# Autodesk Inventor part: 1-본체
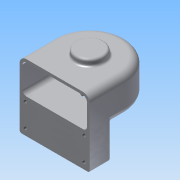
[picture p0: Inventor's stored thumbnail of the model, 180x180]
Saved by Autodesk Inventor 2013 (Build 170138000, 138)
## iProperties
Created: 2015-02
Part Number: 1-본체
Material: 알루미늄 6061
Document SubType Name: Modeling
Designer: Administrator
Density: 2.71 g/cm^3
Mass: 565.472 g
Surface Area: 719.016 cm^2
Volume: 208.661 cm^3
Author: Administrator
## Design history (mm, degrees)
sketch "스케치1"
  geometry: L1 (-50, 0)-(-50, -50); L2 (50, -50)-(50, 0); L3 (-50, -50)-(50, -50); L4 (-34.641, -20)-(-50, -20); L5 (34.641, -20)-(50, -20); L6 (-34.641, -20)-(-34.641, -50); L7 (34.641, -20)-(34.641, -50); A1 r 50 centre (0, 0) between (-50, 0) and (50, 0); A2 r 40 centre (0, 0) between (-34.641, -20) and (34.641, -20); 1 further point
  constraints: 14 end point, 5 perpendicular, 4 point on circle, 4 point on line, 3 tangent, 2 centre point, 2 coincident, 1 collinear, 1 parallel, 1 vertical
  dimensions: "d0" = 50 radius of A1; "d3" = 40 radius of A2; "d4" = 30 distance between parallel lines of L3 L4
extrude "돌출1" new body sketch "스케치1" distance "d5" = 50; taper "d6" = 0 deg
feature "쉘1" dims "d9" = 4
extrude "돌출2" join sketch "스케치1" distance "d7" = 45; taper "d8" = 0 deg
sketch "스케치2"
  geometry: C1 r 25 at (0, 0); A1 r 50 centre (0, 0) between (50, 0) and (-50, 0) reference; A2 r 40 centre (0, 0) between (-34.641, -20) and (34.641, -20) reference
  constraints: 2 coincident, 1 centre point
  dimensions: "d10" = 50 diameter of C1
extrude "돌출3" join sketch "스케치2" distance "d12" = 10; taper "d13" = -20 deg
sketch "스케치3"
  geometry: C1 r 20 at (0, 0); A1 r 50 centre (0, 0) between (50, 0) and (-50, 0) reference
  constraints: 1 centre point, 1 coincident
  dimensions: "d14" = 40 diameter of C1
extrude "돌출4" join sketch "스케치3" distance "d16" = 9; taper "d17" = 0 deg
hole "구멍1" diameter "d20" = 20; stored, may be unused: countersink angle "d24" = 90 deg, drill point angle "d26" = 0 deg; dims "d18" = 10, "d19" = 10, "d21" = 6, "d22" = 28, "d23" = 10, "d25" = 14
hole "구멍2" diameter "d29" = 20; stored, may be unused: countersink angle "d33" = 90 deg, drill point angle "d35" = 0 deg; dims "d27" = 10, "d28" = 10, "d30" = 6, "d31" = 28, "d32" = 8, "d34" = 10
sketch "스케치4"
  geometry: C1 r 14 at (0, 0) reference; C2 r 21.36 at (0, 0) reference; A1 r 18 centre (0, 0) between (0, 18) and (18, 0); 2 further points
  constraints: 4 point on circle, 2 horizontal alignment, 2 vertical alignment, 1 centre point, 1 coincident
  dimensions: "d36" = 36 diameter of A1
hole "구멍3" sketch "스케치4" at (0, 18), (18, 0), (0, -18), (-18, 0) diameter "d38" = 2.459; stored, may be unused: countersink angle "d42" = 90 deg, drill point angle "d44" = 118 deg; dims "d39" = 6, "d40" = 28, "d41" = 8, "d43" = 9
fillet "모깎기2" dims "d46" = 10
fillet "모깎기3" dims "d47" = 3
fillet "모깎기4" dims "d48" = 3
fillet "모깎기5" dims "d49" = 3
chamfer "모따기1" distance "d50" = 1; stored, may be unused: second distance "d51" = 2, angle "d52" = 45 deg
fillet "모깎기6" dims "d53" = 0.3
sketch "스케치5"
  geometry: L1 (87, -95)-(-7, -95) reference; 6 further points
  constraints: 2 horizontal alignment, 2 vertical alignment, 1 midpoint
  dimensions: "d54" = 9 distance from line of L1 point (-1.75, -86); "d55" = 33 distance of point (-1.75, -86) point (-1.75, -53); "d56" = 83.5 distance of point (81.75, -86) point (-1.75, -86); "d57" = 41.75 horizontal distance of point (-1.75, -86) point (40, -95)
hole "구멍4" sketch "스케치5" at (-1.75, -53), (-1.75, -86), (81.75, -53), (81.75, -86) diameter "d58" = 5.134; stored, may be unused: countersink angle "d62" = 90 deg, drill point angle "d64" = 118 deg; dims "d59" = 10, "d60" = 28, "d61" = 8, "d63" = 13
node "작업 평면1"
sketch "스케치6"
  geometry: L1 (-40, 50)-(40, 50) reference; 3 further points
  constraints: 1 midpoint, 1 vertical alignment, 1 other
  dimensions: "d66" = 25 distance from line of point (0, 25) L1
feature "엠보싱1" sketch "스케치6" dims "d0" = 50, "d3" = 40, "d4" = 30, "d67" = 0.5, "d68" = 0
fillet "모깎기7" dims "d69" = 6
node "솔리드1"
other parameters: "d65" = 88
